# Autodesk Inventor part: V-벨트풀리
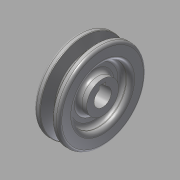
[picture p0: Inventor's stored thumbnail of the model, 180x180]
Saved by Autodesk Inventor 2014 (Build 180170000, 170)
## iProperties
Created: 2015-12
Part Number: V-벨트풀리
Material: 강철, 연강
Document SubType Name: Modeling
Designer: mduedu
Density: 7.86 g/cm^3
Appearance: Steel
Author: mduedu
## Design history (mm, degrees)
sketch "스케치1"
  geometry: L1 (-9.5, 0)-(9.5, 0); L2 (-9.5, 0)-(-9.5, 32.7); L3 (-9.5, 32.7)-(-4.825, 32.7); L4 (-4.825, 32.7)-(-2.074, 23.7); L5 (-2.074, 23.7)-(0, 23.7); L6 (0, 0)-(0, 23.7); L7 (9.5, 0)-(9.5, 32.7); L8 (9.5, 32.7)-(4.825, 32.7); L9 (4.825, 32.7)-(2.074, 23.7); L10 (2.074, 23.7)-(0, 23.7); L11 (-4, 30)-(4, 30); 3 further points
  constraints: 22 end point, 3 coincident, 3 perpendicular, 3 symmetric about line, 2 parallel, 2 point on line, 1 horizontal, 1 midpoint, 1 vertical alignment
  dimensions: "d0" = 19 distance between parallel lines of L7 L2; "d2" = 6.3 distance between parallel lines of L10 L11; "d3" = 34 deg angle of L9 L4; "d4" = 2.7 distance between parallel lines of L11 L8; "d5" = 60 diameter of L11 L1; "d6" = 8 distance of L11.end L11.start
revolve "회전1" sketch "스케치1" stored, may be unused: angle "d7" = 90 deg
sketch "스케치2"
  geometry: C1 r 21 at (0, 0); C2 r 12 at (0, 0); 1 further point
  constraints: 2 centre point, 2 coincident
  dimensions: "d8" = 42 diameter of C1; "d10" = 24 diameter of C2
extrude "돌출1" cut sketch "스케치2" distance "d11" = 6.5; taper "d12" = 0 deg
fillet "모깎기1" dims "d13" = 1, "d14" = 0.5, "d15" = 2
fillet "모깎기2" dims "d16" = 3
fillet "모깎기3" dims "d17" = 3
hole "구멍1" diameter "d20" = 13; stored, may be unused: countersink angle "d24" = 90 deg, drill point angle "d26" = 118 deg; dims "d18" = 10, "d19" = 10, "d21" = 6, "d22" = 4, "d23" = 2, "d25" = 8
sketch "스케치3"
  geometry: L1 (-2.5, 0)-(2.5, 0); L2 (2.5, 0)-(2.5, 8.8); L3 (2.5, 8.8)-(-2.5, 8.8); L4 (-2.5, 8.8)-(-2.5, 0); 2 further points
  constraints: 8 end point, 2 parallel, 1 coincident, 1 horizontal, 1 midpoint, 1 perpendicular
  dimensions: "d27" = 8.8 distance of L1.end L2.end; "d29" = 5 distance of L2.end L3.end
extrude "돌출2" cut sketch "스케치3" stored distance "d30" = 6.5; taper "d31" = 0 deg
node "솔리드1"
mirror "대칭1"
